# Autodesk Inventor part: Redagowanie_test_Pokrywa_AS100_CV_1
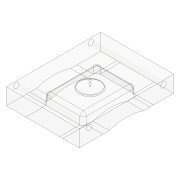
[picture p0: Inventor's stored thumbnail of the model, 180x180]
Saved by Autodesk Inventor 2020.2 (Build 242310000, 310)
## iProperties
Created: 2015-11
Part Number: Redagowanie_test_Pokrywa_AS100_CV_1
Material: Ogólne
Document SubType Name: Modeling
Designer: F.Stasiak
Density: 1 g/cm^3
Appearance: Domyślne
Catalog Web Link: www.expertbooks.pl
Manager: www.cadconsulting.pl
Company: Fabian Stasiak CAD Consulting
Author: F.Stasiak
Subject: Zbiór ćwiczeń. Autodesk Inventor 2020. Kurs Professional
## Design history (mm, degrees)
node "Redagowanie_test_Pokrywa_AS100_CV_Base"
feature "Rzeźbienie4"
feature "Rzeźbienie5"
feature "Rzeźbienie6"
feature "Bryła2::Redagowanie_test_Pokrywa_AS100_CV_Base"
tag "Bryła wyprowadzona2"
node "Bryła2"
feature "Redagowanie_test_Pokrywa_AS100_CV_Base_Bodies"
feature "Powierzchnia4"
body "Srf4"
feature "Powierzchnia5"
body "Srf5"
feature "Powierzchnia6"
body "Srf6"
